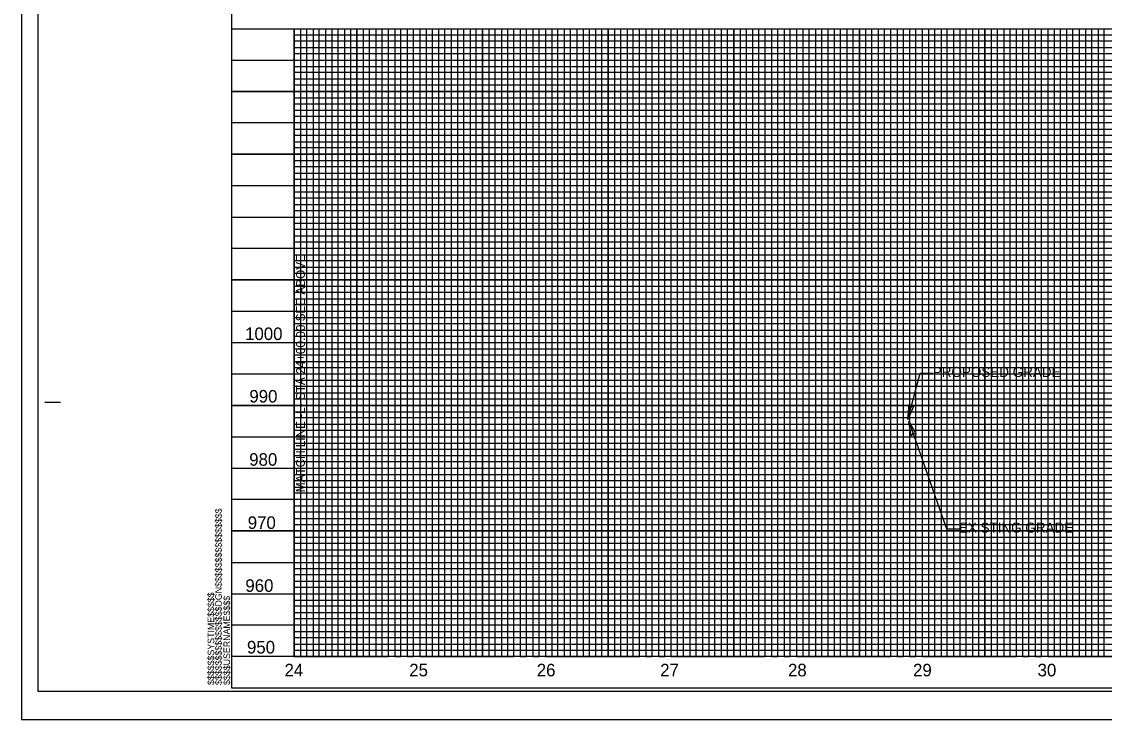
# Model space of a CAD drawing. Extents: x 1623313 to 1628771, y 891211 to 901910.
# Drawn here: x 1623313 to 1624175, y 900759 to 901315 of the extents above; entities that cross this region are included whole.
import ezdxf

# ---------------------------------------------------------------- set-up
doc = ezdxf.new("R2010")
doc.units = 0
for name, color, linetype in [('Default', 7, 'Continuous'), ('Matchline', 7, 'Continuous'), ('Matchline Text', 7, 'Continuous'), ('Prop DSN Text', 7, 'Continuous'), ('Sheet Cutting Line CELL', 7, 'Continuous'), ('Sheet DOT Grid CELL', 7, 'Continuous'), ('Sheet Layout Profile Border Port 2', 7, 'Continuous'), ('Sheet Plot Border Inside CELL', 7, 'Continuous'), ('Sheet Plot Border Outside CELL', 7, 'Continuous'), ('Sheet Profile CELL', 7, 'Continuous'), ('Sheet Profile Grid Major CELL', 7, 'Continuous'), ('Sheet Profile Grid Middle CELL', 7, 'Continuous'), ('Sheet Profile Grid Minor CELL', 7, 'Continuous'), ('Typical Terminator CELL', 7, 'Continuous')]:
    doc.layers.add(name, color=color, linetype=linetype)

msp = doc.modelspace()

# ---------------------------------------------------------------- linework, layer by layer
at = {"layer": 'Matchline'}
msp.add_line((1623529.95, 901309.54), (1623529.95, 900809.54), dxfattribs=at)
at = {"layer": 'Prop DSN Text'}
for points in [[(1624018.41, 900998.26), (1624028.41, 901035.09), (1624038.41, 901035.09)], [(1624019.2, 900996.94), (1624049.2, 900911.12), (1624059.4, 900911.12)]]:
    msp.add_lwpolyline(points, dxfattribs=at)
at = {"layer": 'Sheet Cutting Line CELL'}
for p, q in [((1623312.95, 901859.45), (1623312.95, 900759.45)), ((1623312.95, 900759.45), (1624996.95, 900759.45))]:
    msp.add_line(p, q, dxfattribs=at)
at = {"layer": 'Sheet DOT Grid CELL'}
for p, q in [((1623479.95, 901309.45), (1624979.83, 901309.45)), ((1623529.95, 901309.45), (1623529.95, 900809.45)), ((1623579.95, 901309.45), (1623579.95, 900809.45)), ((1623629.95, 901309.45), (1623629.95, 900809.45)), ((1623679.95, 901309.45), (1623679.95, 900809.45)), ((1623729.95, 901309.45), (1623729.95, 900809.45)), ((1623779.95, 901309.45), (1623779.95, 900809.45)), ((1623829.95, 901309.45), (1623829.95, 900809.45)), ((1623879.95, 901309.45), (1623879.95, 900809.45)), ((1623929.95, 901309.45), (1623929.95, 900809.45)), ((1623979.95, 901309.45), (1623979.95, 900809.45)), ((1624029.95, 901309.45), (1624029.95, 900809.45)), ((1624079.95, 901309.45), (1624079.95, 900809.45)), ((1624129.95, 901309.45), (1624129.95, 900809.45)), ((1623479.95, 901259.45), (1624979.83, 901259.45)), ((1623479.95, 901209.45), (1624979.83, 901209.45)), ((1623479.95, 901159.45), (1624979.83, 901159.45)), ((1623479.95, 901109.45), (1624979.83, 901109.45)), ((1623479.95, 901059.45), (1624979.83, 901059.45)), ((1623479.95, 901009.45), (1624979.83, 901009.45)), ((1623479.95, 900959.45), (1624979.83, 900959.45)), ((1623479.95, 900909.45), (1624979.83, 900909.45)), ((1623479.95, 900859.45), (1624979.83, 900859.45))]:
    msp.add_line(p, q, dxfattribs=at)
at = {"layer": 'Sheet Layout Profile Border Port 2'}
msp.add_lwpolyline([(1623529.95, 901309.45), (1624929.95, 901309.45), (1624929.95, 900809.45), (1623529.95, 900809.45)], close=True, dxfattribs=at)
at = {"layer": 'Sheet Plot Border Inside CELL'}
msp.add_lwpolyline([(1623325.95, 900781.9), (1624992.45, 900781.9), (1624992.45, 901837), (1623325.95, 901837)], close=True, dxfattribs=at)
at = {"layer": 'Sheet Plot Border Outside CELL'}
msp.add_lwpolyline([(1623312.95, 900759.45), (1624996.95, 900759.45), (1624996.95, 901859.45), (1623312.95, 901859.45)], close=True, dxfattribs=at)
at = {"layer": 'Sheet Profile CELL'}
for p, q in [((1623479.95, 901309.45), (1624979.95, 901309.45)), ((1623331.45, 901011.95), (1623343.95, 901011.95)), ((1624979.95, 900809.45), (1623479.95, 900809.45)), ((1623479.95, 900784.45), (1624979.95, 900784.45)), ((1623479.95, 900784.45), (1623479.95, 900784.45)), ((1623479.95, 900784.45), (1623479.95, 900784.45)), ((1623479.95, 900784.45), (1623479.95, 900784.45)), ((1623479.95, 900784.45), (1623479.95, 900784.45)), ((1623479.95, 900784.45), (1623479.95, 900784.45)), ((1623479.95, 900784.45), (1623479.95, 900784.45)), ((1623479.95, 900784.45), (1623479.95, 900784.45))]:
    msp.add_line(p, q, dxfattribs=at)
msp.add_lwpolyline([(1624979.95, 901834.45), (1623479.95, 901834.45), (1623479.95, 900784.45), (1624979.95, 900784.45)], close=True, dxfattribs=at)
msp.add_lwpolyline([(1623517.45, 900784.45), (1623517.45, 900784.45)], dxfattribs=at)
at = {"layer": 'Sheet Profile Grid Major CELL'}
for p, q in [((1623979.95, 901309.45), (1624029.95, 901309.45)), ((1624079.95, 901309.45), (1624129.95, 901309.45)), ((1623479.95, 900809.45), (1623479.95, 900809.45))]:
    msp.add_line(p, q, dxfattribs=at)
for points in [[(1623529.95, 901309.45), (1623529.95, 900809.45), (1623579.95, 900809.45), (1623579.95, 901309.45), (1623629.95, 901309.45), (1623629.95, 900809.45), (1623679.95, 900809.45), (1623679.95, 901309.45), (1623729.95, 901309.45), (1623729.95, 900809.45), (1623779.95, 900809.45), (1623779.95, 901309.45), (1623829.95, 901309.45), (1623829.95, 900809.45), (1623879.95, 900809.45), (1623879.95, 901309.45), (1623929.95, 901309.45), (1623929.95, 900809.45), (1623979.95, 900809.45), (1623979.95, 901309.45), (1624029.95, 901309.45), (1624029.95, 900809.45), (1624079.95, 900809.45), (1624079.95, 901309.45), (1624129.95, 901309.45), (1624129.95, 900809.45), (1624179.95, 900809.45)], [(1624979.95, 901259.45), (1623479.95, 901259.45)], [(1624979.95, 901209.45), (1623479.95, 901209.45), (1623479.95, 901159.45), (1624979.95, 901159.45)], [(1624979.95, 901109.45), (1623479.95, 901109.45), (1623479.95, 901059.45), (1624979.95, 901059.45)], [(1624979.95, 901009.45), (1623479.95, 901009.45), (1623479.95, 900959.45), (1624979.95, 900959.45)], [(1624979.95, 900909.45), (1623479.95, 900909.45), (1623479.95, 900909.45), (1623479.95, 900859.45), (1624979.95, 900859.45)], [(1624979.95, 900809.45), (1623479.95, 900809.45)]]:
    msp.add_lwpolyline(points, dxfattribs=at)
at = {"layer": 'Sheet Profile Grid Middle CELL'}
for points in [[(1623504.95, 901309.45), (1623554.95, 901309.45), (1623554.95, 900809.45), (1623604.95, 900809.45), (1623604.95, 901309.45), (1623654.95, 901309.45), (1623654.95, 900809.45), (1623704.95, 900809.45), (1623704.95, 901309.45), (1623754.95, 901309.45), (1623754.95, 900809.45), (1623804.95, 900809.45), (1623804.95, 901309.45), (1623854.95, 901309.45), (1623854.95, 900809.45), (1623904.95, 900809.45), (1623904.95, 901309.45), (1623954.95, 901309.45), (1623954.95, 900809.45), (1624004.95, 900809.45), (1624004.95, 901309.45), (1624054.95, 901309.45), (1624054.95, 900809.45), (1624104.95, 900809.45), (1624104.95, 900809.45), (1624104.95, 901309.45), (1624154.95, 901309.45), (1624154.95, 900809.45), (1624204.95, 900809.45)], [(1623479.95, 901284.45), (1624979.95, 901284.45)], [(1624979.95, 901234.45), (1623479.95, 901234.45), (1623479.95, 901184.45), (1624979.95, 901184.45)], [(1624979.95, 901134.45), (1623479.95, 901134.45), (1623479.95, 901084.45), (1624979.95, 901084.45)], [(1624979.95, 901034.45), (1623479.95, 901034.45), (1623479.95, 900984.45), (1624979.95, 900984.45)], [(1624979.95, 900934.45), (1623479.95, 900934.45), (1623479.95, 900884.45), (1624979.95, 900884.45)], [(1624979.95, 900834.45), (1623479.95, 900834.45)]]:
    msp.add_lwpolyline(points, dxfattribs=at)
at = {"layer": 'Sheet Profile Grid Minor CELL'}
for p, q in [((1623529.95, 901304.45), (1624929.95, 901304.45)), ((1624929.95, 901299.45), (1623529.95, 901299.45)), ((1623529.95, 901294.45), (1624929.95, 901294.45)), ((1624929.95, 901289.45), (1623529.95, 901289.45)), ((1623529.95, 901279.45), (1624929.95, 901279.45)), ((1624929.95, 901274.45), (1623529.95, 901274.45)), ((1623529.95, 901269.45), (1624929.95, 901269.45)), ((1624929.95, 901264.45), (1623529.95, 901264.45)), ((1623529.95, 901254.45), (1624929.95, 901254.45)), ((1624929.95, 901249.45), (1623529.95, 901249.45)), ((1623529.95, 901244.45), (1624929.95, 901244.45)), ((1624929.95, 901239.45), (1623529.95, 901239.45)), ((1623529.95, 901229.45), (1624929.95, 901229.45)), ((1624929.95, 901224.45), (1623529.95, 901224.45)), ((1623529.95, 901219.45), (1624929.95, 901219.45)), ((1624929.95, 901214.45), (1623529.95, 901214.45)), ((1623529.95, 901204.45), (1624929.95, 901204.45)), ((1624929.95, 901199.45), (1623529.95, 901199.45)), ((1623529.95, 901194.45), (1624929.95, 901194.45)), ((1624929.95, 901189.45), (1623529.95, 901189.45)), ((1623529.95, 901179.45), (1624929.95, 901179.45)), ((1624929.95, 901174.45), (1623529.95, 901174.45)), ((1623529.95, 901169.45), (1624929.95, 901169.45)), ((1624929.95, 901164.45), (1623529.95, 901164.45)), ((1623529.95, 901154.45), (1624929.95, 901154.45)), ((1624929.95, 901149.45), (1623529.95, 901149.45)), ((1623529.95, 901144.45), (1624929.95, 901144.45)), ((1624929.95, 901139.45), (1623529.95, 901139.45)), ((1623529.95, 901129.45), (1624929.95, 901129.45)), ((1624929.95, 901124.45), (1623529.95, 901124.45)), ((1623529.95, 901119.45), (1624929.95, 901119.45)), ((1624929.95, 901114.45), (1623529.95, 901114.6)), ((1623529.95, 901104.45), (1624929.95, 901104.45)), ((1624929.95, 901099.45), (1623529.95, 901099.45)), ((1623529.95, 901094.45), (1624929.95, 901094.45)), ((1624929.95, 901089.45), (1623529.95, 901089.45)), ((1623529.95, 901079.45), (1624929.95, 901079.45)), ((1624929.95, 901074.45), (1623529.95, 901074.45)), ((1623529.95, 901069.45), (1624929.95, 901069.45)), ((1624929.95, 901064.45), (1623529.95, 901064.45)), ((1623529.95, 901054.45), (1624929.95, 901054.45)), ((1624929.95, 901049.45), (1623529.95, 901049.45)), ((1623529.95, 901044.45), (1624929.95, 901044.45)), ((1624929.95, 901039.45), (1623529.95, 901039.45)), ((1623529.95, 901029.45), (1624929.95, 901029.45)), ((1624929.95, 901024.45), (1623529.95, 901024.45)), ((1623529.95, 901019.45), (1624929.95, 901019.45)), ((1624929.95, 901014.45), (1623529.95, 901014.45)), ((1623529.95, 901004.45), (1624929.95, 901004.45)), ((1624929.95, 900999.45), (1623529.95, 900999.45)), ((1623529.95, 900994.45), (1624929.95, 900994.45)), ((1624929.95, 900989.45), (1623529.95, 900989.45)), ((1623529.95, 900979.45), (1624929.95, 900979.45)), ((1624929.95, 900974.45), (1623529.95, 900974.45)), ((1623529.95, 900969.45), (1624929.95, 900969.45)), ((1624929.95, 900964.45), (1623529.95, 900964.45)), ((1623529.95, 900954.45), (1624929.95, 900954.45)), ((1624929.95, 900949.45), (1623529.95, 900949.45)), ((1623529.95, 900944.45), (1624929.95, 900944.45)), ((1624929.95, 900939.45), (1623529.95, 900939.45)), ((1623529.95, 900929.45), (1624929.95, 900929.45)), ((1624929.95, 900924.45), (1623529.95, 900924.45)), ((1623529.95, 900919.45), (1624929.95, 900919.45)), ((1624929.95, 900914.45), (1623529.95, 900914.45)), ((1623529.95, 900904.45), (1624929.95, 900904.45)), ((1624929.95, 900899.45), (1623529.95, 900899.45)), ((1623529.95, 900894.45), (1624929.95, 900894.45)), ((1624929.95, 900889.45), (1623529.95, 900889.45)), ((1623529.95, 900879.45), (1624929.95, 900879.45)), ((1624929.95, 900874.45), (1623529.95, 900874.45)), ((1623529.95, 900869.45), (1624929.95, 900869.45)), ((1624929.95, 900864.45), (1623529.95, 900864.45)), ((1623529.95, 900854.45), (1624929.95, 900854.45)), ((1624929.95, 900849.45), (1623529.95, 900849.45)), ((1623529.95, 900844.45), (1624929.95, 900844.45)), ((1624929.95, 900839.45), (1623529.95, 900839.45)), ((1623529.95, 900829.45), (1624929.95, 900829.45)), ((1624929.95, 900824.45), (1623529.95, 900824.45)), ((1623529.95, 900819.45), (1624929.95, 900819.45)), ((1623529.95, 900814.45), (1624929.95, 900814.45))]:
    msp.add_line(p, q, dxfattribs=at)
for points in [[(1623529.95, 901309.45), (1623534.95, 901309.45), (1623534.95, 900809.45), (1623539.95, 900809.45), (1623539.95, 901309.45), (1623544.95, 901309.45), (1623544.95, 900809.45), (1623549.95, 900809.45), (1623549.95, 901309.45), (1623559.95, 901309.45), (1623559.95, 900809.45), (1623564.95, 900809.45), (1623564.95, 901309.45), (1623569.95, 901309.45), (1623569.95, 900809.45), (1623574.95, 900809.45), (1623584.95, 900809.45), (1623589.95, 900809.45), (1623589.95, 901309.45), (1623594.95, 901309.45), (1623594.95, 900809.45), (1623599.95, 900809.45), (1623599.95, 901309.45), (1623609.95, 901309.45), (1623609.95, 900809.45), (1623614.95, 900809.45), (1623614.95, 901309.45), (1623619.95, 901309.45), (1623619.95, 900809.45), (1623624.95, 900809.45), (1623624.95, 901309.45), (1623634.95, 901309.45), (1623634.95, 900809.45), (1623639.95, 900809.45), (1623639.95, 901309.45), (1623644.95, 901309.45), (1623644.95, 900809.45), (1623649.95, 900809.45), (1623649.95, 901309.45), (1623659.95, 901309.45), (1623659.95, 900809.45), (1623664.95, 900809.45), (1623664.95, 901309.45), (1623669.95, 901309.45), (1623669.95, 900809.45), (1623674.95, 900809.45), (1623674.95, 901309.45), (1623684.95, 901309.45), (1623684.95, 900809.45), (1623689.95, 900809.45), (1623689.95, 901309.45), (1623694.95, 901309.45), (1623694.95, 900809.45), (1623699.95, 900809.45), (1623699.95, 901309.45), (1623709.95, 901309.45), (1623709.95, 900809.45), (1623714.95, 900809.45), (1623714.95, 901309.45), (1623719.95, 901309.45), (1623719.95, 900809.45), (1623724.95, 900809.45), (1623724.95, 901309.45), (1623734.95, 901309.45), (1623734.95, 900809.45), (1623739.95, 900809.45), (1623739.95, 901309.45), (1623744.95, 901309.45), (1623744.95, 900809.45)], [(1623574.95, 900809.45), (1623574.95, 901309.45), (1623584.95, 901309.45), (1623584.95, 900809.45)], [(1623744.95, 900809.45), (1623749.95, 900809.45), (1623749.95, 901309.45), (1623759.95, 901309.45), (1623759.95, 900809.45), (1623764.95, 900809.45), (1623764.95, 901309.45), (1623769.95, 901309.45), (1623769.95, 900809.45), (1623774.95, 900809.45), (1623774.95, 901309.45), (1623784.95, 901309.45), (1623784.95, 900809.45), (1623789.95, 900809.45), (1623789.95, 901309.45), (1623794.95, 901309.45), (1623794.95, 900809.45), (1623799.95, 900809.45), (1623799.95, 901309.45), (1623809.95, 901309.45), (1623809.95, 900809.45), (1623814.95, 900809.45), (1623814.95, 901309.45), (1623819.95, 901309.45), (1623819.95, 900809.45), (1623824.95, 900809.45), (1623824.95, 901309.45), (1623834.95, 901309.45), (1623834.95, 900809.45), (1623839.95, 900809.45), (1623839.95, 901309.45), (1623844.95, 901309.45), (1623844.95, 900809.45), (1623849.95, 900809.45), (1623849.95, 901309.45), (1623859.95, 901309.45), (1623859.95, 900809.45), (1623864.95, 900809.45), (1623864.95, 901309.45), (1623869.95, 901309.45), (1623869.95, 900809.45), (1623874.95, 900809.45), (1623874.95, 901309.45), (1623884.95, 901309.45), (1623884.95, 900809.45), (1623889.95, 900809.45), (1623889.95, 901309.45), (1623894.95, 901309.45), (1623894.95, 900809.45), (1623899.95, 900809.45), (1623899.95, 901309.45), (1623909.95, 901309.45), (1623909.95, 900809.45), (1623914.95, 900809.45), (1623914.95, 901309.45), (1623919.95, 901309.45), (1623919.95, 900809.45), (1623924.95, 900809.45), (1623924.95, 901309.45), (1623934.95, 901309.45), (1623934.95, 900809.45), (1623939.95, 900809.45), (1623939.95, 901309.45), (1623944.95, 901309.45), (1623944.95, 900809.45), (1623949.95, 900809.45), (1623949.95, 901309.45), (1623959.95, 901309.45), (1623959.95, 900809.45), (1623964.95, 900809.45), (1623964.95, 901309.45), (1623969.95, 901309.45), (1623969.95, 900809.45), (1623974.95, 900809.45), (1623974.95, 901309.45), (1623984.95, 901309.45), (1623984.95, 900809.45), (1623989.95, 900809.45), (1623989.95, 901309.45), (1623994.95, 901309.45), (1623994.95, 900809.45), (1623999.95, 900809.45), (1623999.95, 901309.45), (1624009.95, 901309.45), (1624009.95, 900809.45), (1624014.95, 900809.45), (1624014.95, 901309.45), (1624019.95, 901309.45), (1624019.95, 900809.45), (1624024.95, 900809.45), (1624024.95, 901309.45), (1624034.95, 901309.45), (1624034.95, 900809.45), (1624039.95, 900809.45), (1624039.95, 901309.45), (1624044.95, 901309.45), (1624044.95, 900809.45), (1624049.95, 900809.45), (1624049.95, 901309.45), (1624059.95, 901309.45)], [(1624059.95, 901309.45), (1624059.95, 900809.45), (1624064.95, 900809.45), (1624064.95, 901309.45), (1624069.95, 901309.45), (1624069.95, 900809.45), (1624074.95, 900809.45), (1624074.95, 901309.45), (1624084.95, 901309.45), (1624084.95, 900809.45), (1624089.95, 900809.45), (1624089.95, 901309.45), (1624094.95, 901309.45), (1624094.95, 900809.45), (1624099.95, 900809.45), (1624099.95, 901309.45), (1624109.95, 901309.45), (1624109.95, 900809.45), (1624114.95, 900809.45), (1624114.95, 901309.45), (1624119.95, 901309.45), (1624119.95, 900809.45), (1624124.95, 900809.45), (1624124.95, 901309.45), (1624134.95, 901309.45), (1624134.95, 900809.45), (1624139.95, 900809.45), (1624139.95, 901309.45), (1624144.95, 901309.45), (1624144.95, 900809.45), (1624149.95, 900809.45), (1624149.95, 901309.45), (1624159.95, 901309.45), (1624159.95, 900809.45), (1624164.95, 900809.45), (1624164.95, 901309.45), (1624169.95, 901309.45), (1624169.95, 900809.45), (1624174.95, 900809.45), (1624174.95, 901309.45), (1624184.95, 901309.45)]]:
    msp.add_lwpolyline(points, dxfattribs=at)
at = {"layer": 'Typical Terminator CELL'}
for points in [[(1624023.42, 901009.04), (1624018.41, 900998.26), (1624019.48, 901010.18), (1624021.1, 901008.19)], [(1624021.16, 900985.22), (1624019.2, 900996.94), (1624025.05, 900986.51), (1624022.59, 900987.23)]]:
    msp.add_lwpolyline(points, close=True, dxfattribs=at)

# ---------------------------------------------------------------- texts
at = {"layer": 'Default'}
for s, p in [('1000', (1623490.88, 901061.5)), ('990', (1623494.27, 901011.72)), ('980', (1623494.15, 900961.42)), ('970', (1623492.99, 900911.08)), ('960', (1623491.09, 900860.98)), ('950', (1623492.37, 900811.9)), ('24', (1623522.26, 900793.69)), ('25', (1623621.55, 900793.69)), ('26', (1623723.09, 900793.69)), ('27', (1623821.36, 900793.69)), ('28', (1623923.12, 900793.69)), ('29', (1624022.68, 900793.69)), ('30', (1624121.85, 900793.69))]:
    msp.add_text(s, height=10, dxfattribs=at).set_placement(p)
at = {"layer": 'Matchline Text'}
msp.add_text('MATCH LINE -L- STA 24+00.00 SEE ABOVE', height=7, rotation=90, dxfattribs=at).set_placement((1623538.45, 900940.32))
at = {"layer": 'Prop DSN Text'}
for s, p in [('PROPOSED GRADE', (1624038.41, 901032.09)), ('EXISTING GRADE', (1624059.2, 900908.12))]:
    msp.add_text(s, height=8, dxfattribs=at).set_placement(p)
at = {"layer": 'Sheet Profile CELL'}
for s, p in [('$$$$$$$$$$$$$$$$DGN$$$$$$$$$$$$$$$$', (1623472.31, 900786.82)), ('$$$$$$SYSTIME$$$$$', (1623466.26, 900786.82)), ('$$$$USERNAME$$$$', (1623478.88, 900786.84))]:
    msp.add_text(s, height=5.25, rotation=90, dxfattribs=at).set_placement(p)

doc.saveas('drawing.dxf')
